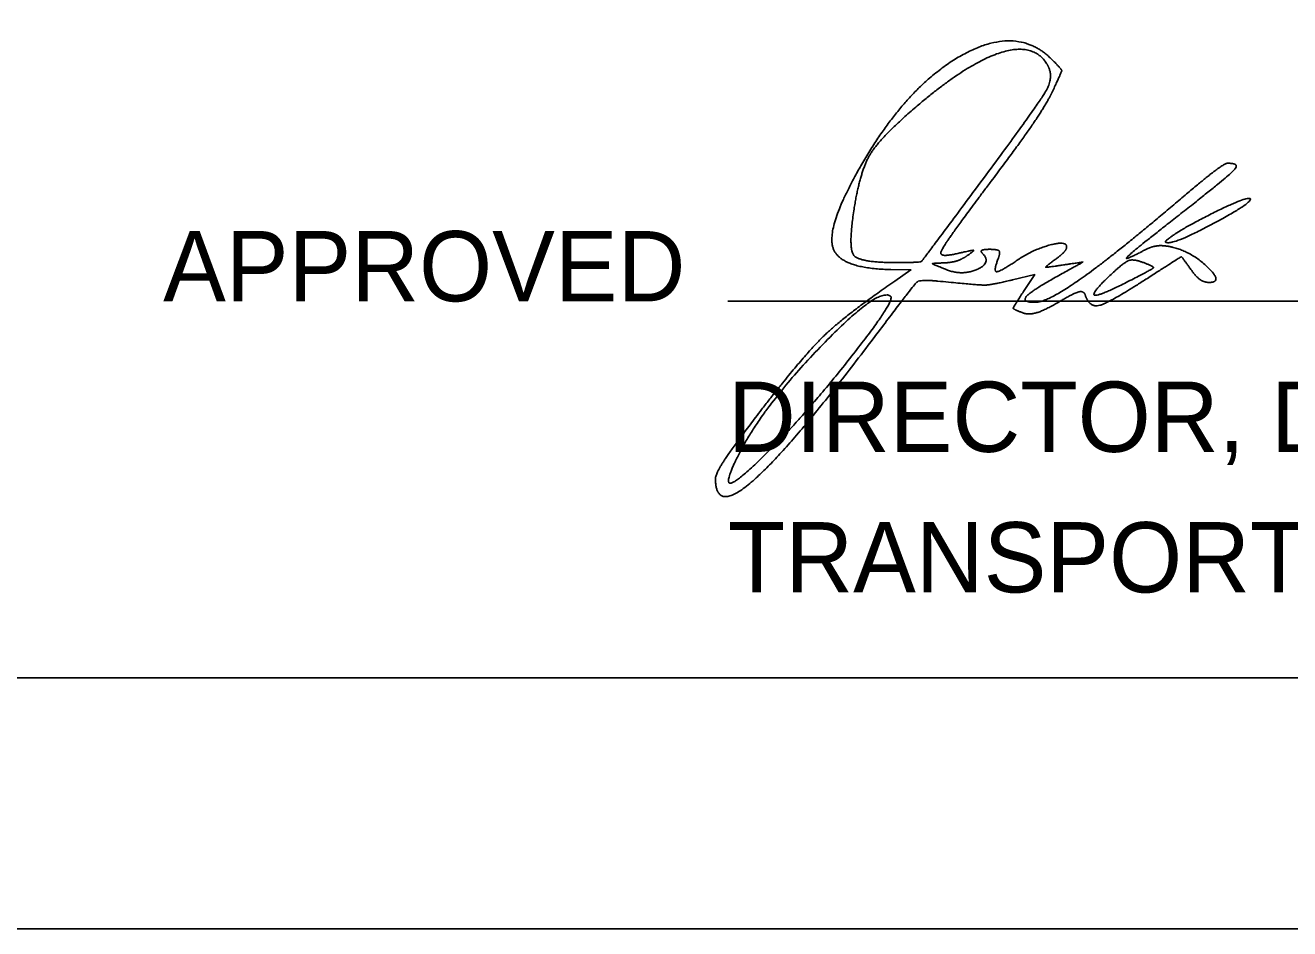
# Model space of a CAD drawing. Extents: x 0 to 2329303, y 0 to 694397.
# Drawn here: x 25.225 to 27.744, y 0 to 1.8 of the extents above; entities that cross this region are included whole.
import ezdxf

# ---------------------------------------------------------------- set-up
doc = ezdxf.new("R2010")
doc.units = 0
for name, color, linetype in [('SH_Border', 7, 'Continuous'), ('SH_Cut_Line', 7, 'Continuous'), ('SH_Data', 7, 'Continuous'), ('SH_Text', 7, 'Continuous')]:
    doc.layers.add(name, color=color, linetype=linetype)

msp = doc.modelspace()

# ---------------------------------------------------------------- linework, layer by layer
at = {"layer": 'SH_Border'}
msp.add_lwpolyline([(1.5, 21.5), (33.5, 21.5), (33.5, 0.5), (1.5, 0.5)], close=True, dxfattribs=at)
at = {"layer": 'SH_Cut_Line'}
msp.add_lwpolyline([(0, 0), (34, 0), (34, 22), (0, 22)], close=True, dxfattribs=at)
at = {"layer": 'SH_Data'}
msp.add_line((26.625, 1.25), (31.5, 1.25), dxfattribs=at)
at = {"layer": 'SH_Text'}
for p, q in [((27.1132, 1.4665), (27.1132, 1.4665)), ((27.499, 1.3716), (27.499, 1.3716)), ((27.4517, 1.3276), (27.4517, 1.3276))]:
    msp.add_line(p, q, dxfattribs=at)
for points in [[(26.9573, 1.2902), (26.9897, 1.3126), (26.9497, 1.3133)], [(27.2138, 1.2693), (27.2362, 1.3034), (27.1921, 1.2928)]]:
    msp.add_lwpolyline(points, dxfattribs=at)
for points in [[(26.89, 1.5201), (26.9811, 1.6789), (27.2009, 1.8015), (27.2702, 1.7321)], [(27.2608, 1.7224), (27.2334, 1.7668), (27.1002, 1.7233), (26.9995, 1.6371)], [(27.1132, 1.4665), (27.2413, 1.6391), (27.2756, 1.6985), (27.2608, 1.7224)], [(27.2702, 1.7321), (27.2901, 1.7123), (27.2901, 1.707), (27.2708, 1.6664)], [(27.2708, 1.6664), (27.2592, 1.6421), (27.2046, 1.5623), (27.1494, 1.4891)], [(26.9995, 1.6371), (26.9291, 1.5769), (26.8881, 1.5092), (26.8764, 1.4339)], [(26.9497, 1.3133), (26.8463, 1.3151), (26.8216, 1.4008), (26.89, 1.5201)], [(27.5132, 1.4425), (27.5665, 1.4878), (27.6145, 1.5249), (27.62, 1.525)], [(27.62, 1.525), (27.6462, 1.5255), (27.6216, 1.4986), (27.5309, 1.4275)], [(27.1494, 1.4891), (27.0942, 1.4158), (27.0491, 1.3518), (27.0491, 1.3467)], [(26.9589, 1.3272), (27.0082, 1.3272), (27.013, 1.3316), (27.1132, 1.4665)], [(27.2372, 1.248), (27.2616, 1.248), (27.3947, 1.3418), (27.5132, 1.4425)], [(27.499, 1.3716), (27.5205, 1.3905), (27.6599, 1.4599), (27.6654, 1.4545)], [(27.6654, 1.4545), (27.6719, 1.448), (27.5213, 1.3668), (27.5027, 1.3668)], [(26.8764, 1.4339), (26.8644, 1.3565), (26.887, 1.3272), (26.9589, 1.3272)], [(27.5309, 1.4275), (27.4324, 1.3504), (27.4098, 1.3277), (27.4561, 1.3525)], [(27.2012, 1.3318), (27.2317, 1.3527), (27.2999, 1.3712), (27.2999, 1.3586)], [(27.4561, 1.3525), (27.4695, 1.3596), (27.4947, 1.3618), (27.5122, 1.3574)], [(27.5027, 1.3668), (27.4976, 1.3668), (27.496, 1.369), (27.499, 1.3716)], [(27.0491, 1.3467), (27.0491, 1.3417), (27.0654, 1.3413), (27.0854, 1.346)], [(27.1019, 1.341), (27.091, 1.3336), (27.0702, 1.3272), (27.0557, 1.3266)], [(27.0601, 1.3132), (27.0916, 1.3005), (27.151, 1.3265), (27.1326, 1.3449)], [(27.0854, 1.346), (27.1123, 1.3522), (27.1166, 1.351), (27.1019, 1.341)], [(27.1326, 1.3449), (27.1278, 1.3497), (27.1344, 1.3536), (27.1473, 1.3536)], [(27.1473, 1.3536), (27.1627, 1.3536), (27.1681, 1.3468), (27.1631, 1.3338)], [(27.2999, 1.3586), (27.2999, 1.3538), (27.2896, 1.3424), (27.277, 1.3332)], [(27.5471, 1.3137), (27.5293, 1.3391), (27.5272, 1.3386), (27.4577, 1.2939)], [(27.5122, 1.3574), (27.5504, 1.3477), (27.612, 1.2876), (27.5838, 1.2876)], [(27.0557, 1.3266), (27.032, 1.3257), (27.0325, 1.3243), (27.0601, 1.3132)], [(27.1631, 1.3338), (27.1537, 1.3093), (27.1672, 1.3086), (27.2012, 1.3318)], [(27.277, 1.3332), (27.2571, 1.3186), (27.2592, 1.3173), (27.2935, 1.3225)], [(27.2935, 1.3225), (27.3324, 1.3283), (27.3322, 1.3281), (27.2842, 1.3015)], [(27.3956, 1.3102), (27.3488, 1.2674), (27.3607, 1.258), (27.422, 1.2893)], [(27.4517, 1.3276), (27.4335, 1.3343), (27.4161, 1.3289), (27.3956, 1.3102)], [(27.422, 1.2893), (27.4709, 1.3143), (27.4747, 1.3192), (27.4517, 1.3276)], [(27.5838, 1.2876), (27.5737, 1.2876), (27.5572, 1.2993), (27.5471, 1.3137)], [(26.6923, 1.0345), (26.7743, 1.1406), (26.8588, 1.2222), (26.9573, 1.2902)], [(27.043, 1.2903), (27.0077, 1.2938), (26.9953, 1.2828), (26.9144, 1.1754)], [(27.1921, 1.2928), (27.1495, 1.2825), (27.1259, 1.2821), (27.043, 1.2903)], [(27.2842, 1.3015), (27.2303, 1.2717), (27.2095, 1.248), (27.2372, 1.248)], [(27.4577, 1.2939), (27.385, 1.247), (27.3454, 1.2367), (27.3369, 1.2625)], [(26.9497, 1.2594), (26.9277, 1.2814), (26.6969, 1.0431), (26.648, 0.9477)], [(27.2125, 1.227), (27.1933, 1.2343), (27.1935, 1.2382), (27.2138, 1.2693)], [(27.3369, 1.2625), (27.3339, 1.2715), (27.3135, 1.266), (27.2828, 1.2479)], [(26.722, 0.9675), (26.7934, 1.0405), (26.9579, 1.2512), (26.9497, 1.2594)], [(27.2828, 1.2479), (27.2558, 1.2319), (27.2242, 1.2225), (27.2125, 1.227)], [(26.9144, 1.1754), (26.7535, 0.962), (26.6003, 0.8262), (26.6003, 0.8969)], [(26.6003, 0.8969), (26.6003, 0.9071), (26.6417, 0.969), (26.6923, 1.0345)], [(26.648, 0.9477), (26.615, 0.8833), (26.6484, 0.8923), (26.722, 0.9675)]]:
    msp.add_open_spline(points, degree=2, dxfattribs=at)

# ---------------------------------------------------------------- texts
at = {"layer": 'SH_Data'}
for s, p in [('APPROVED', (25.5, 1.25)), ('DIRECTOR, DEPARTMENT OF', (26.625, 0.95)), ('TRANSPORTATION', (26.625, 0.67))]:
    msp.add_text(s, height=0.14, dxfattribs=at).set_placement(p)

doc.saveas('drawing.dxf')
